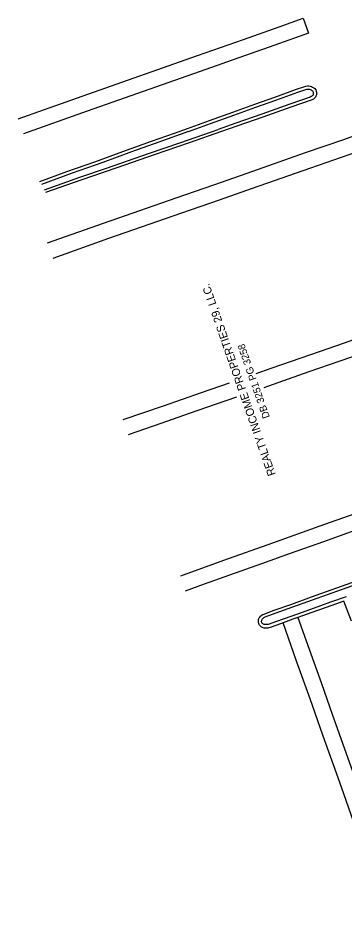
# Model space of a CAD drawing. Extents: x 1611576 to 1617186, y 899279 to 905462.
# Drawn here: x 1615960 to 1616163, y 903268 to 903833 of the extents above; entities that cross this region are included whole.
import ezdxf

# ---------------------------------------------------------------- set-up
doc = ezdxf.new("R2010")
doc.units = 0
for name, color, linetype in [('Exist Property Deed Book Text', 7, 'Continuous'), ('Exist Property Owner Text', 7, 'Continuous'), ('Exist Roads Change in Surface', 7, 'Continuous'), ('Exist Roads Curbs', 7, 'Continuous'), ('Exist Roads EOP Other', 7, 'Continuous')]:
    doc.layers.add(name, color=color, linetype=linetype)

msp = doc.modelspace()

# ---------------------------------------------------------------- linework, layer by layer
at = {"layer": 'Exist Roads Change in Surface'}
for points in [[(1615959.53, 903769.73), (1615976.04, 903775.6), (1616002.92, 903785.1), (1616071.43, 903809.24), (1616100.07, 903819.42), (1616122.41, 903827.29), (1616137.4, 903832.72), (1616140.69, 903823.33), (1616119.55, 903815.83), (1616096.53, 903807.65), (1616076.57, 903800.6), (1616002.66, 903774.54), (1615962.86, 903760.48)], [(1615977.86, 903692.4), (1616012.69, 903704.67), (1616058.14, 903720.5), (1616081.62, 903728.6), (1616102.28, 903735.77), (1616138.67, 903748.68), (1616162.62, 903756.97), (1616173.49, 903760.81), (1616192.57, 903767.41)], [(1615981.36, 903682.64), (1616016.19, 903695.14), (1616061.6, 903710.95), (1616085.09, 903719.1), (1616105.67, 903726.37), (1616142.12, 903739.16), (1616166.07, 903747.45), (1616176.95, 903751.26), (1616196.01, 903757.85)], [(1616108.1, 903610.72), (1616117.38, 903613.98), (1616142.18, 903622.65), (1616163.07, 903629.88), (1616177.06, 903634.82), (1616200.42, 903642.96), (1616221.92, 903650.51), (1616233.01, 903654.38)], [(1616236.41, 903644.88), (1616224.78, 903640.85), (1616203.53, 903633.48), (1616180.2, 903625.29), (1616160.1, 903618.3), (1616140.93, 903611.63), (1616121.49, 903604.78), (1616112.78, 903601.76)], [(1616025.15, 903581.84), (1616050.24, 903590.49), (1616073.89, 903598.8), (1616091.45, 903604.89)], [(1616095.65, 903595.82), (1616082.5, 903591.22), (1616066.11, 903585.63), (1616049.17, 903579.71), (1616028.15, 903572.42)], [(1616060.94, 903484.38), (1616087.87, 903493.99), (1616118.3, 903504.85), (1616147.36, 903515.29), (1616169.81, 903523.28), (1616193.6, 903531.82), (1616217.32, 903540.16), (1616239.89, 903548.29), (1616267.38, 903558.1)], [(1616270.82, 903548.66), (1616254.85, 903542.98), (1616230.55, 903534.33), (1616208.57, 903526.5), (1616188.38, 903519.26), (1616169.62, 903512.65), (1616150, 903505.59), (1616129.27, 903498.23), (1616111.38, 903491.87), (1616091.43, 903484.7), (1616075.62, 903478.99), (1616063.69, 903474.75)], [(1616190.84, 903268.07), (1616180.44, 903297.77), (1616170.19, 903326.74), (1616162.59, 903348.18), (1616158.09, 903360.94), (1616149.61, 903384.78), (1616141.62, 903407.46), (1616133.24, 903431.04), (1616124.75, 903454.92)], [(1616134.07, 903458.31), (1616141.15, 903438.39), (1616148.72, 903417), (1616155.49, 903397.77), (1616159.68, 903385.61), (1616168.32, 903361.53), (1616175.61, 903341.1), (1616182.28, 903322.4), (1616189.28, 903302.43), (1616194.53, 903287.7), (1616200.26, 903271.48), (1616190.84, 903268.07)]]:
    msp.add_lwpolyline(points, dxfattribs=at)
at = {"layer": 'Exist Roads Curbs'}
for points in [[(1616065.85, 903761.83), (1616079.57, 903766.83), (1616094.06, 903772.03), (1616107.83, 903777), (1616120.22, 903781.44), (1616133.91, 903786.35), (1616138.96, 903788.1), (1616139.51, 903788.26), (1616140.06, 903788.34), (1616140.63, 903788.35), (1616141.19, 903788.27), (1616141.73, 903788.11), (1616142.25, 903787.88), (1616142.73, 903787.58), (1616143.1, 903787.27), (1616143.35, 903786.91), (1616143.52, 903786.51), (1616143.62, 903786.08), (1616143.64, 903785.64), (1616143.58, 903785.21), (1616143.45, 903784.79), (1616143.24, 903784.41), (1616142.96, 903784.07), (1616142.63, 903783.78), (1616142.38, 903783.63), (1616141.6, 903783.26), (1616129, 903778.97), (1616111.57, 903772.78), (1616095.33, 903767.06), (1616084.35, 903763.18)], [(1616065.85, 903761.83), (1616047.32, 903755.18), (1616030.26, 903749.06), (1616012.29, 903742.6), (1615993.33, 903735.77), (1615974.05, 903728.79)], [(1615975.99, 903725.48), (1615997.94, 903733.28), (1616014.64, 903738.86), (1616040.84, 903748.17), (1616060.97, 903754.97), (1616084.35, 903763.18)], [(1616164.04, 903471.22), (1616154.37, 903467.73), (1616141.95, 903463.31), (1616130.22, 903459.05), (1616120.07, 903455.47), (1616116.07, 903454.06), (1616115.38, 903453.89), (1616114.68, 903453.81), (1616113.97, 903453.8), (1616113.41, 903453.85), (1616112.95, 903453.95), (1616112.52, 903454.12), (1616112.12, 903454.37), (1616111.81, 903454.64), (1616111.59, 903454.91), (1616111.44, 903455.22), (1616111.36, 903455.55), (1616111.36, 903455.9), (1616111.37, 903455.98), (1616111.45, 903456.43), (1616111.6, 903456.86), (1616111.83, 903457.26), (1616111.91, 903457.37), (1616112.31, 903457.8), (1616112.77, 903458.17), (1616113.27, 903458.48), (1616113.65, 903458.66), (1616119.89, 903461.01), (1616130.89, 903464.86), (1616143.07, 903469.2), (1616161.87, 903475.91), (1616174.79, 903480.56)]]:
    msp.add_lwpolyline(points, dxfattribs=at)
at = {"layer": 'Exist Roads EOP Other'}
for points in [[(1616057.05, 903760.85), (1616065.17, 903763.76), (1616078.89, 903768.72), (1616093.38, 903773.92), (1616107.15, 903778.89), (1616119.55, 903783.33), (1616133.24, 903788.24), (1616138.35, 903790.01), (1616139.07, 903790.23), (1616139.91, 903790.35), (1616140.76, 903790.36), (1616141.6, 903790.24), (1616142.42, 903790.01), (1616143.2, 903789.66), (1616143.91, 903789.21), (1616144.61, 903788.63), (1616145.12, 903787.88), (1616145.44, 903787.14), (1616145.62, 903786.36), (1616145.66, 903785.55), (1616145.55, 903784.76), (1616145.3, 903783.99), (1616144.91, 903783.29), (1616144.41, 903782.66), (1616143.82, 903782.16), (1616143.34, 903781.86), (1616142.35, 903781.39), (1616129.66, 903777.07), (1616112.24, 903770.89), (1616096, 903765.17), (1616086.38, 903761.77)], [(1615973.07, 903730.71), (1615989.9, 903736.78), (1616007.41, 903743), (1616024.82, 903749.31), (1616042.67, 903755.76), (1616057.05, 903760.85)], [(1616086.38, 903761.77), (1616066.22, 903754.71), (1616044.28, 903747.2), (1616021.16, 903739.2), (1615998.68, 903731.37), (1615976.56, 903723.75)], [(1616112.41, 903460.2), (1616119.26, 903462.79), (1616130.25, 903466.65), (1616142.44, 903471.07), (1616161.26, 903477.76), (1616174.15, 903482.38)], [(1616167.38, 903456.01), (1616162.69, 903468.52), (1616155.18, 903465.8), (1616142.7, 903461.39), (1616134.07, 903458.31), (1616130.93, 903457.19), (1616124.75, 903454.92), (1616120.84, 903453.49), (1616116.71, 903452.03)], [(1616116.71, 903452.03), (1616115.97, 903451.8), (1616115.2, 903451.64), (1616114.42, 903451.57), (1616113.64, 903451.57), (1616113.02, 903451.63), (1616112.45, 903451.77), (1616111.9, 903452), (1616111.39, 903452.29), (1616110.92, 903452.65), (1616110.5, 903453.07), (1616110.15, 903453.54), (1616109.94, 903453.89), (1616109.69, 903454.43), (1616109.51, 903455.01), (1616109.41, 903455.6), (1616109.38, 903456.21), (1616109.44, 903456.81), (1616109.47, 903456.99), (1616109.65, 903457.54), (1616109.9, 903458.06), (1616110.21, 903458.54), (1616110.6, 903458.98), (1616110.91, 903459.26), (1616111.46, 903459.67), (1616112.05, 903460.03), (1616112.41, 903460.2)]]:
    msp.add_lwpolyline(points, dxfattribs=at)

# ---------------------------------------------------------------- texts
at = {"layer": 'Exist Property Deed Book Text'}
msp.add_text('DB 3251 PG 3258', height=4.5, rotation=109.1768, dxfattribs=at).set_placement((1616116.58, 903583.49))
at = {"layer": 'Exist Property Owner Text'}
msp.add_text('REALTY INCOME PROPERTIES 29, LLC.', height=5, rotation=109.1768, dxfattribs=at).set_placement((1616120.25, 903547.71))

doc.saveas('drawing.dxf')
